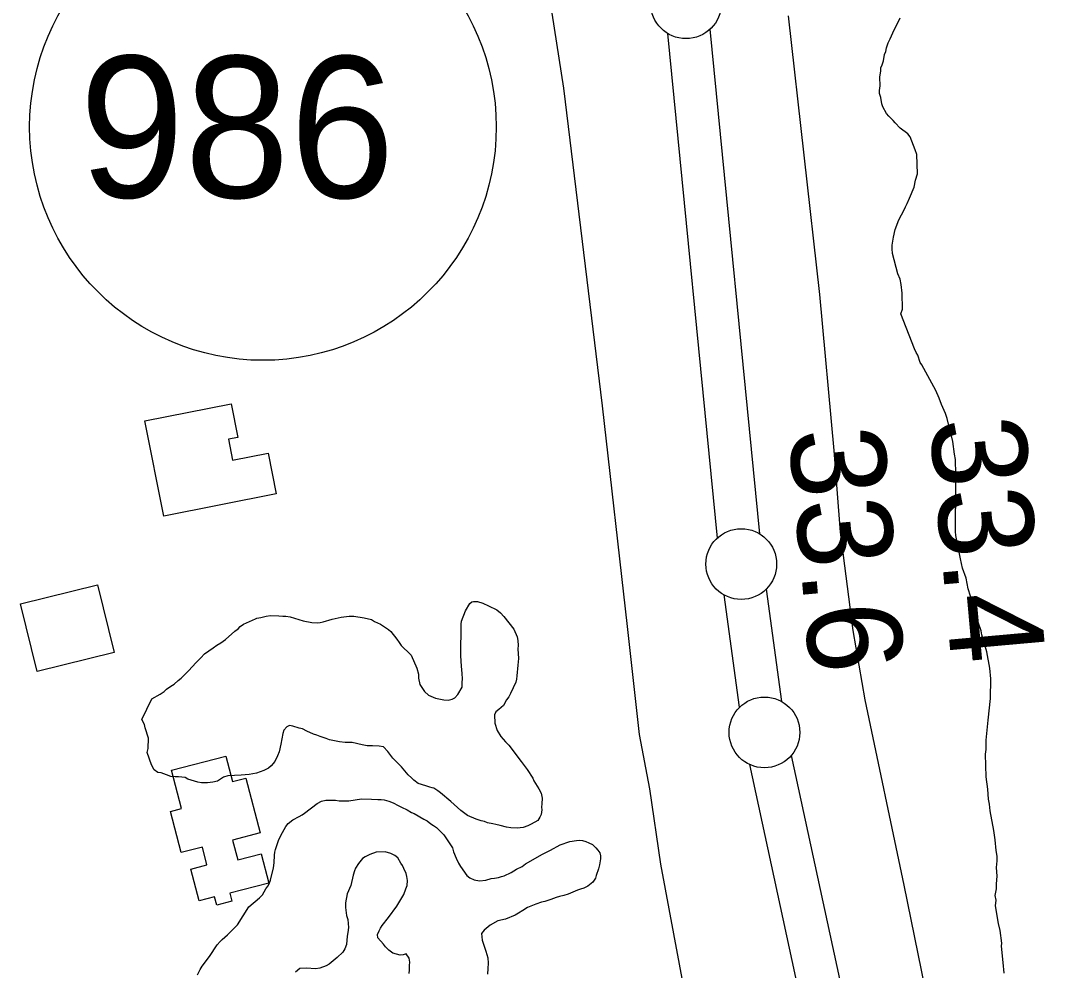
# Model space of a CAD drawing. Extents: x 3313442 to 3351311, y 721974 to 747360.
# Drawn here: x 3321453 to 3322177, y 728787 to 729459 of the extents above; entities that cross this region are included whole.
import ezdxf

# ---------------------------------------------------------------- set-up
doc = ezdxf.new("R2010")
doc.units = 0
for name, color, linetype in [('V-BLDG-OTLN', 7, 'Continuous'), ('V-LEVE-TOET', 7, 'Continuous'), ('V-RIVR-RANG', 7, 'Continuous'), ('V-ROAD-IDEN', 7, 'Continuous'), ('V-SITE-VEGE', 7, 'Continuous'), ('V-SURV-LINE', 7, 'Continuous')]:
    doc.layers.add(name, color=color, linetype=linetype)

msp = doc.modelspace()

# ---------------------------------------------------------------- linework, layer by layer
at = {"layer": 'V-BLDG-OTLN'}
for points in [[(3321554.13, 729108.46), (3321540.73, 729175.82), (3321601.7, 729187.94), (3321606.44, 729164.07), (3321599.82, 729162.76), (3321602.77, 729147.94), (3321627.9, 729152.94), (3321633.61, 729124.27)], [(3321464.53, 728998.6), (3321452.76, 729046.35), (3321507.29, 729059.79), (3321519.05, 729012.03)], [(3321622.29, 728884.45), (3321602.74, 728879.37), (3321606.37, 728865.4), (3321622.92, 728869.71), (3321628.31, 728848.96), (3321600.89, 728841.83), (3321602.34, 728836.27), (3321591.6, 728833.47), (3321590.07, 728839.36), (3321579.08, 728836.51), (3321573.25, 728858.91), (3321584.65, 728861.88), (3321581.37, 728874.47), (3321566.32, 728870.55), (3321558.75, 728899.64), (3321566.54, 728901.67), (3321559.49, 728928.76), (3321597.95, 728938.76), (3321602.63, 728920.8), (3321612.19, 728923.28)]]:
    msp.add_lwpolyline(points, close=True, dxfattribs=at)
at = {"layer": 'V-LEVE-TOET'}
for points in [[(3321820.23, 729517.4), (3321836.84, 729411.07), (3321864.18, 729186.43), (3321881.71, 729030.41), (3321890.41, 728954.14), (3321897.71, 728915.54), (3321905.4, 728862.29), (3321914.53, 728813.04), (3321936.11, 728698.3)], [(3322107.35, 728701.91), (3322077.69, 728847.59), (3322050.16, 728978.61), (3322041.56, 729027.68), (3322032.62, 729096.98), (3322028.29, 729154.72), (3322018, 729265.18), (3321995.97, 729462.22)]]:
    msp.add_lwpolyline(points, dxfattribs=at)
at = {"layer": 'V-ROAD-IDEN'}
msp.add_circle((3321624.26, 729383.59), 165, dxfattribs=at)
msp.add_circle((3321624.26, 729383.59), 165, dxfattribs=at)
at = {"layer": 'V-SITE-VEGE'}
for points in [[(3322075.35, 729251.54), (3322076.62, 729254.83), (3322076.31, 729265.98), (3322075.55, 729272.18), (3322074.76, 729275.9), (3322073.14, 729279.63), (3322069.56, 729294.1), (3322069.18, 729297.41), (3322069.21, 729299.89), (3322070.09, 729305.65), (3322071.38, 729311.01), (3322073.92, 729318), (3322077.7, 729324.98), (3322078.54, 729327.03), (3322079.8, 729329.5), (3322081.49, 729333.2), (3322084.86, 729341.01), (3322085.73, 729345.95), (3322087.02, 729350.48), (3322086.73, 729364.1), (3322085.53, 729367.41), (3322081.9, 729376.52), (3322080.27, 729378.6), (3322074.94, 729382.78), (3322071.26, 729386.53), (3322070.04, 729388.19), (3322066.77, 729391.11), (3322065.14, 729393.19), (3322062.7, 729397.75), (3322061.9, 729399.82), (3322061.11, 729404.37), (3322060.32, 729407.27), (3322060.33, 729409.33), (3322060.78, 729412.63), (3322060.42, 729418.82), (3322061.29, 729423.35), (3322061.31, 729425.42), (3322062.16, 729427.47), (3322063.01, 729430.35), (3322063.88, 729434.88), (3322064.72, 729436.94), (3322065.16, 729439.41), (3322066.43, 729443.11), (3322067.7, 729445.99), (3322069.8, 729450.1), (3322074.85, 729460.78)], [(3322148.53, 728785.35), (3322147.78, 728792.78), (3322146.65, 728804.35), (3322146.67, 728806.41), (3322145.52, 728815.51), (3322144.33, 728820.47), (3322142.38, 728832.86), (3322142.83, 728836.99), (3322142.04, 728840.3), (3322142.91, 728844.83), (3322142.94, 728848.54), (3322143.4, 728853.9), (3322143.05, 728860.1), (3322143.5, 728864.63), (3322143.54, 728867.93), (3322142.75, 728872.07), (3322141.99, 728879.5), (3322141.23, 728886.11), (3322138.48, 728900.17), (3322138.1, 728904.71), (3322137.32, 728908.44), (3322136.97, 728915.45), (3322135.81, 728924.13), (3322135.14, 728940.23), (3322135.58, 728943.53), (3322135.65, 728950.13), (3322137.02, 728964.15), (3322138.81, 728979.4), (3322138.95, 728993.43), (3322138.19, 729000.87), (3322136.23, 729012.44), (3322132.64, 729024.44), (3322132.25, 729027.33), (3322130.24, 729032.72), (3322127.83, 729040.17), (3322127.02, 729042.24), (3322126.23, 729045.14), (3322124.64, 729051.75), (3322123.04, 729057.13), (3322121.46, 729064.58), (3322119.05, 729071.61), (3322117.46, 729078.23), (3322114.31, 729094.77), (3322113.93, 729097.66), (3322114.01, 729106.33), (3322114.15, 729121.18), (3322114.32, 729138.93), (3322113.99, 729147.6), (3322114, 729148.42), (3322113.21, 729152.14), (3322112.05, 729161.23), (3322108.08, 729177.37), (3322106.88, 729181.09), (3322104.05, 729187.31), (3322102.44, 729191.86), (3322100.01, 729197.25), (3322090.28, 729215.5), (3322089.06, 729217.16), (3322087.46, 729222.13), (3322086.24, 729224.2), (3322085.02, 729226.69), (3322075.35, 729251.54)], [(3321538.63, 728964.62), (3321545.61, 728979.25), (3321551.46, 728982.48), (3321554.27, 728984.48), (3321556.06, 728985.98), (3321559.12, 728988.23), (3321561.41, 728989.73), (3321564.22, 728992.24), (3321566.51, 728993.99), (3321571.62, 728999.01), (3321577, 729005.04), (3321580.32, 729008.29), (3321582.88, 729011.05), (3321589, 729015.3), (3321591.55, 729017.3), (3321594.35, 729018.8), (3321597.66, 729021.3), (3321604.3, 729027.06), (3321606.6, 729028.81), (3321608.13, 729030.31), (3321610.43, 729032.06), (3321619.07, 729035.78), (3321619.84, 729036.28), (3321622.63, 729036.76), (3321626.44, 729037.74), (3321629.48, 729038.22), (3321635.55, 729037.91), (3321638.34, 729037.63), (3321640.36, 729037.61), (3321643.4, 729037.33), (3321652.74, 729034.45), (3321658.81, 729033.13), (3321662.6, 729033.09), (3321664.63, 729033.33), (3321666.92, 729033.81), (3321673.26, 729035.52), (3321679.61, 729036.98), (3321685.18, 729037.69), (3321688.48, 729037.66), (3321695.81, 729036.58), (3321701.12, 729035.26), (3321703.13, 729033.97), (3321707.42, 729032.16), (3321712.95, 729028.31), (3321714.71, 729026.78), (3321718.96, 729021.42), (3321720.46, 729019.12), (3321721.96, 729017.08), (3321724.22, 729014.78), (3321726.48, 729012.74), (3321728.99, 729010.18), (3321732.95, 729001.03), (3321734.18, 728996.71), (3321734.15, 728993.92), (3321735.12, 728989.36), (3321738.37, 728984.52), (3321741.38, 728981.96), (3321746.17, 728979.63), (3321752.24, 728978.56), (3321755.27, 728978.28), (3321758.07, 728979.01), (3321759.85, 728980.01), (3321762.15, 728982.27), (3321765.24, 728987.56), (3321765.02, 728990.85), (3321765.29, 728993.38), (3321765.08, 728997.18), (3321764.62, 729002.25), (3321764.18, 729009.6), (3321764.39, 729032.13), (3321764.66, 729034.15), (3321767.52, 729041.47), (3321770.61, 729046.76), (3321771.88, 729047.76), (3321773.15, 729048), (3321775.94, 729047.97), (3321779.73, 729046.93), (3321783.76, 729045.12), (3321789.56, 729042.28), (3321792.32, 729039.97), (3321794.58, 729037.42), (3321801.58, 729028.49), (3321804.07, 729023.15), (3321804.55, 729020.61), (3321804.77, 729017.06), (3321804.49, 729014.53), (3321804.93, 729007.69), (3321804.39, 729003.14), (3321803.81, 728995.55), (3321803.53, 728993.27), (3321803, 728991), (3321799.38, 728982.93), (3321798.09, 728980.66), (3321796.56, 728978.65), (3321794.24, 728974.62), (3321791.17, 728971.61), (3321788.88, 728970.11), (3321788.1, 728967.84), (3321788.29, 728962.01)], [(3321795.77, 728948.77), (3321798.02, 728946.47), (3321799.78, 728944.43), (3321801.78, 728941.88), (3321806.78, 728934.99), (3321811.03, 728929.39), (3321815.02, 728923.27), (3321815.76, 728921.24), (3321819.26, 728915.63), (3321821, 728912.58), (3321821.73, 728909.03), (3321821.44, 728904.98), (3321821.16, 728902.7), (3321821.39, 728900.67), (3321821.11, 728897.38), (3321820.08, 728895.62), (3321818.54, 728893.35), (3321813.96, 728890.61), (3321811.67, 728889.37), (3321808.37, 728888.39), (3321804.05, 728887.92), (3321799.5, 728887.96), (3321796.46, 728888.5), (3321791.92, 728889.81), (3321788.88, 728890.34), (3321786.86, 728890.87), (3321783.07, 728891.66), (3321780.8, 728892.45), (3321778.52, 728892.97), (3321774.99, 728894.27), (3321768.94, 728896.86), (3321766.93, 728898.15), (3321764.16, 728900.2), (3321757.13, 728906.6), (3321749.84, 728912.74), (3321747.83, 728914.28), (3321745.06, 728916.08), (3321743.8, 728916.35), (3321742.29, 728916.87), (3321739.51, 728917.65), (3321733.96, 728919.48), (3321730.94, 728921.79), (3321729.18, 728923.32), (3321726.92, 728925.62), (3321722.16, 728931.24), (3321716.14, 728937.37), (3321712.64, 728941.96), (3321709.38, 728945.29), (3321706.35, 728945.82), (3321701.79, 728946.12), (3321697.99, 728946.15), (3321694.46, 728946.69), (3321687.38, 728948.28), (3321682.31, 728948.33), (3321678.27, 728948.87), (3321671.19, 728950.2), (3321668.92, 728951.24), (3321664.63, 728952.54), (3321662.36, 728953.58), (3321660.09, 728954.36), (3321655.29, 728956.43), (3321652.27, 728957.98), (3321649.75, 728958.51), (3321645.45, 728959.82), (3321642.92, 728960.35), (3321641.14, 728959.35), (3321639.1, 728957.09), (3321638.31, 728954.82), (3321636.98, 728947.24), (3321635.66, 728941.68), (3321634.62, 728938.9), (3321632.55, 728934.87), (3321629.99, 728931.85), (3321628.21, 728930.35), (3321624.9, 728928.61), (3321619.56, 728926.63), (3321614.49, 728925.67), (3321608.91, 728925.22), (3321599.29, 728924.8), (3321596.24, 728923.82), (3321592.16, 728921.07), (3321588.86, 728920.34), (3321585.06, 728919.87), (3321580.75, 728919.91), (3321578.23, 728920.44), (3321571.16, 728922.53), (3321569.14, 728923.57), (3321564.59, 728924.11), (3321562.06, 728924.14), (3321559.02, 728924.42), (3321555.99, 728925.46), (3321552.21, 728927.02), (3321549.93, 728927.29), (3321547.42, 728929.09), (3321545.42, 728932.65), (3321542.46, 728941.29), (3321543, 728944.07), (3321543.32, 728951.41), (3321540.86, 728958.78), (3321540.37, 728961.06), (3321538.63, 728964.62)], [(3321788.29, 728962.01), (3321789.77, 728956.94), (3321792.51, 728952.6), (3321795.77, 728948.77)], [(3321614.37, 728832.23), (3321621.77, 728838.49), (3321623.81, 728840.75), (3321625.1, 728842.76), (3321626.39, 728845.03), (3321627.67, 728846.79), (3321628.7, 728848.55), (3321629.48, 728851.08), (3321631.59, 728859.67), (3321632.13, 728863.21), (3321632.44, 728868.78), (3321632.71, 728870.8), (3321633.23, 728872.82), (3321635.32, 728879.13), (3321636.87, 728882.66), (3321640.48, 728888.96), (3321642.02, 728891.22), (3321645.33, 728893.73), (3321649.92, 728895.96), (3321651.95, 728897.21), (3321653.73, 728898.46), (3321662.66, 728905.21), (3321665.72, 728906.95), (3321668.76, 728907.68), (3321675.6, 728907.62), (3321678.13, 728907.09), (3321684.96, 728907.03), (3321693.84, 728908.46), (3321700.93, 728908.39), (3321705.48, 728908.1), (3321707.77, 728908.08), (3321710.04, 728907.8), (3321713.33, 728907.01), (3321716.35, 728905.72), (3321719.88, 728903.91), (3321722.15, 728902.62), (3321726.18, 728900.81), (3321729.2, 728899.01), (3321731.22, 728898.23), (3321738.02, 728894.11), (3321740.29, 728893.08), (3321743.05, 728890.78), (3321744.81, 728889.75), (3321747.08, 728888.21), (3321752.1, 728883.09), (3321758.34, 728873.92), (3321759.07, 728871.13), (3321760.8, 728866.55), (3321762.54, 728862.99), (3321764.04, 728860.7), (3321768.54, 728854.32), (3321770.55, 728852.78), (3321773.57, 728851.24), (3321777.37, 728850.7), (3321781.93, 728851.16), (3321785.74, 728852.14), (3321788.02, 728852.37), (3321790.81, 728852.85), (3321792.84, 728853.59), (3321794.87, 728854.08), (3321799.71, 728856.56), (3321803.52, 728858.8), (3321807.6, 728860.79), (3321809.89, 728862.54), (3321821.86, 728869.52), (3321824.4, 728870.51), (3321827.71, 728872.25), (3321834.33, 728875.99), (3321841.19, 728878.45), (3321846.01, 728879.17), (3321848.29, 728879.4), (3321850.31, 728879.13), (3321852.58, 728878.34), (3321854.6, 728877.57), (3321857.37, 728876.28), (3321859.63, 728873.97), (3321861.14, 728872.19), (3321862.39, 728870.4), (3321862.87, 728868.37), (3321862.85, 728866.09), (3321862.31, 728861.8), (3321861.52, 728859.02), (3321859.96, 728854.47), (3321859.43, 728852.45), (3321857.63, 728849.68), (3321854.06, 728846.93), (3321851.26, 728845.44), (3321848.72, 728844.7), (3321846.69, 728843.96), (3321840.08, 728841.24), (3321837.03, 728840.26), (3321833.98, 728839.53), (3321831.7, 728838.79), (3321827.89, 728837.3), (3321823.57, 728836.08), (3321821.29, 728835.59), (3321817.22, 728834.11), (3321811.37, 728831.64), (3321808.06, 728829.64), (3321805.01, 728827.64), (3321802.71, 728826.4)], [(3321727.62, 728785.07), (3321727.9, 728787.6), (3321727.93, 728790.64), (3321728.2, 728793.17), (3321727.72, 728795.96), (3321725.47, 728799.02), (3321723.44, 728798.28), (3321721.16, 728798.05), (3321716.11, 728799.36), (3321713.34, 728801.67), (3321710.83, 728803.97), (3321709.58, 728805.75), (3321705.58, 728810.35), (3321705.34, 728812.63), (3321706.38, 728815.15), (3321707.41, 728817.17), (3321708.44, 728818.93), (3321713.06, 728824.71), (3321718.95, 728832.76), (3321723.84, 728840.82), (3321725.4, 728844.85), (3321726.18, 728847.38), (3321726.47, 728850.92), (3321725.99, 728853.71), (3321725.5, 728855.74), (3321723.76, 728859.3), (3321723.02, 728861.34), (3321721.77, 728863.12), (3321719.53, 728866.94), (3321717.52, 728868.48), (3321714.75, 728870.02), (3321710.71, 728871.08), (3321704.37, 728870.88), (3321699.8, 728869.15), (3321696.5, 728867.67), (3321694.71, 728866.42), (3321691.89, 728862.9), (3321689.58, 728859.63), (3321689.05, 728857.6), (3321688.01, 728854.58), (3321686.43, 728847.25), (3321683.84, 728841.45), (3321682.51, 728835.13), (3321682.73, 728831.84), (3321683.44, 728826.01), (3321684.17, 728823.21), (3321684.63, 728817.64), (3321684.34, 728814.1), (3321683.81, 728811.57), (3321683.24, 728805.5), (3321682.2, 728802.47), (3321680.66, 728800.2), (3321676.83, 728796.44), (3321670.96, 728791.68), (3321668.92, 728790.44), (3321664.35, 728788.96), (3321661.3, 728788.48), (3321654.98, 728788.8), (3321650.42, 728788.59), (3321647.36, 728786.08)], [(3321577.95, 728784.21), (3321579.76, 728787.99), (3321581.3, 728790.25), (3321586.43, 728797.04), (3321591.83, 728805.35), (3321593.87, 728807.6), (3321595.41, 728809.11), (3321599.24, 728812.37), (3321600.77, 728814.12), (3321606.14, 728819.39), (3321610.25, 728825.94), (3321614.37, 728832.23)], [(3321802.71, 728826.4), (3321795.85, 728823.42), (3321790.27, 728822.21), (3321784.92, 728819.22), (3321780.58, 728815.72), (3321778.79, 728813.46), (3321779.25, 728808.64), (3321781.96, 728800.77), (3321783.18, 728796.2), (3321783.4, 728792.4), (3321783.37, 728788.6), (3321783.07, 728784.55)]]:
    msp.add_lwpolyline(points, dxfattribs=at)
at = {"layer": 'V-SURV-LINE'}
for points in [[(3321945.61, 729092.95), (3321910.47, 729449.67)], [(3321940.33, 729452.62), (3321975.47, 729095.9)], [(3321961.31, 728973.29), (3321950.37, 729052.7)], [(3321980.09, 729056.79), (3321991.03, 728977.37)], [(3321997.79, 728939.17), (3322108.27, 728428.6)], [(3322078.95, 728422.25), (3321968.47, 728932.82)]]:
    msp.add_lwpolyline(points, dxfattribs=at)
for centre in [(3321923.44, 729471.02), (3321962.5, 729074.55), (3321978.9, 728955.53)]:
    msp.add_circle(centre, 25, dxfattribs=at)

# ---------------------------------------------------------------- texts
at = {"layer": 'V-RIVR-RANG'}
for s, p in [('33.4', (3322095.68, 729176.14)), ('33.6', (3321995.94, 729168.82))]:
    msp.add_text(s, height=67, rotation=275.11833, dxfattribs=at).set_placement(p)
at = {"layer": 'V-ROAD-IDEN'}
msp.add_text('986', height=100, rotation=359.9167, dxfattribs=at).set_placement((3321494.27, 729333.78))

doc.saveas('drawing.dxf')
